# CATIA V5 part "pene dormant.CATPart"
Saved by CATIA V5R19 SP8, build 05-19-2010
Part number: pene dormant
Revision: ANY
Definition: UNKNOWN
Nomenclature: pene dormant
Source: Unknown
Bounding box of the stored display mesh (mm): x -1.991 to 60, y -4 to 33, z -3 to 6
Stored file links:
  D:\Documents\1_Travail\1 - ac-limoges.fr\ac-limoges.fr\Emmanuel Maynard - STI2D_Turgot\2 -2I2D\2_SEQUENCE_Serrure_Biométrique\5-Spé_ITEC\Serrure_Bio_Eleve\pene dormant.CATPart
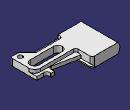
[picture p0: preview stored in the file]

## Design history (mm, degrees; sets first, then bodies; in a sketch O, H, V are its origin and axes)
Body1 "Enlèv. mat.-Extru.3" (main body)
  Solid1: solid without history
